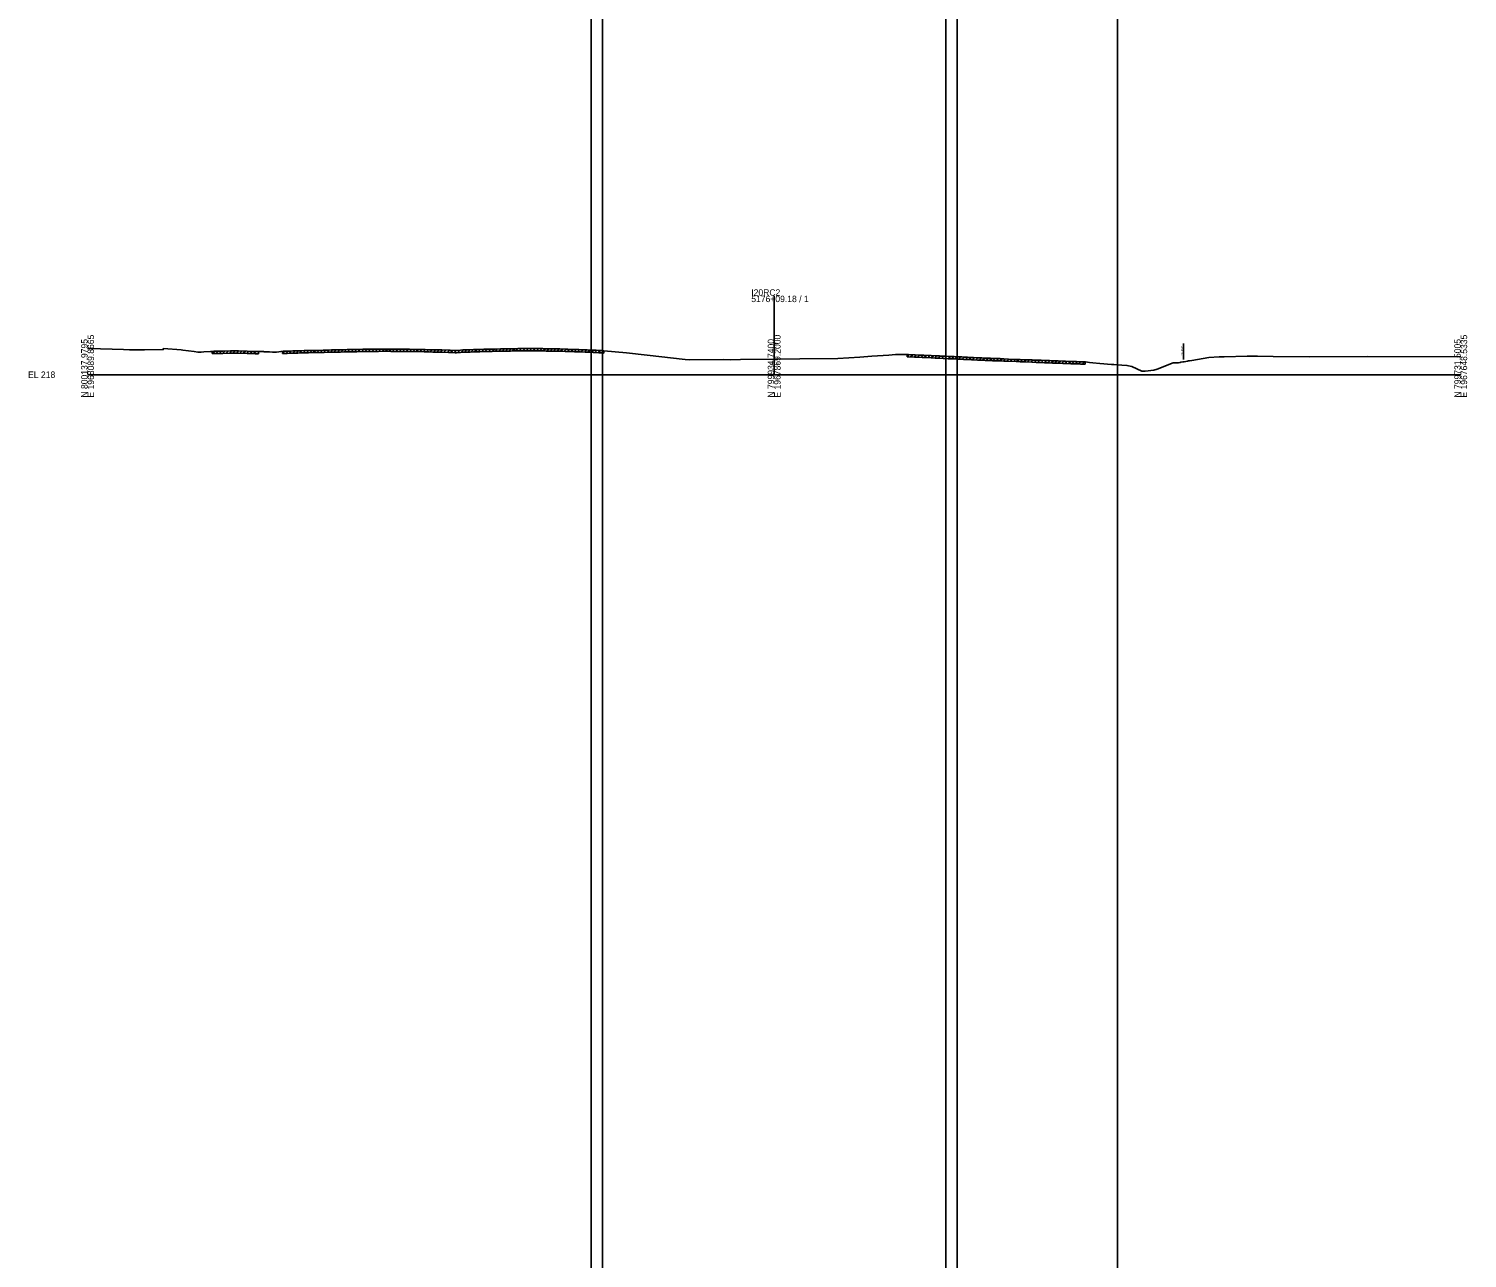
# Model space of a CAD drawing. Extents: x -119 to 6018, y -82 to 34226.
# Drawn here: x -26 to 603, y 32614 to 33151 of the extents above; entities that cross this region are included whole.
import ezdxf

# ---------------------------------------------------------------- set-up
doc = ezdxf.new("R2010")
doc.units = 0
for name, color, linetype in [('Default', 7, 'Continuous'), ('RD_GPK_XS_Cell', 7, 'Continuous'), ('RD_Sketch1', 7, 'Continuous'), ('RD_XS_ExGround', 7, 'Continuous'), ('RD_XS_ExPaveRet', 7, 'Continuous'), ('RD_XS_ExRW', 7, 'Continuous'), ('RD_XS_TX_Elev_EX', 7, 'Continuous'), ('RD_XS_TX_Elev_PR', 7, 'Continuous')]:
    doc.layers.add(name, color=color, linetype=linetype)

msp = doc.modelspace()

# ---------------------------------------------------------------- linework, layer by layer
at = {"layer": 'RD_GPK_XS_Cell'}
for p, q in [((300, 33000), (300, 33034.53)), ((0, 33000), (300, 33000)), ((300, 33000), (600, 33000))]:
    msp.add_line(p, q, dxfattribs=at)
at = {"layer": 'RD_Sketch1'}
for p, q in [((220, -82), (220, 34226.15)), ((225, -82), (225, 34226.15)), ((375, -82), (375, 34226.15)), ((380, -82), (380, 34226.15)), ((450, -82), (450, 34226.15))]:
    msp.add_line(p, q, dxfattribs=at)
at = {"layer": 'RD_XS_ExGround'}
msp.add_lwpolyline([(0, 33011.47), (0.68, 33011.44), (15.74, 33011.05), (18.27, 33010.9), (24.81, 33010.9), (33.08, 33011.01), (33.18, 33011.51), (40.95, 33010.82), (41.69, 33010.74), (46.51, 33010.1), (48.14, 33009.86), (48.48, 33009.83), (49.2, 33009.88), (49.63, 33009.91), (50.78, 33009.99), (53.67, 33010.19), (54.16, 33010.2), (55.13, 33010.23), (55.72, 33010.24), (59.13, 33010.33), (62.52, 33010.4), (64.05, 33010.42), (65.99, 33010.46), (69.68, 33010.31), (72.98, 33010.2), (73.35, 33010.19), (74.85, 33010.14), (76.07, 33010.09), (76.83, 33010.07), (77.22, 33010.05), (77.94, 33010.02), (79.51, 33009.96), (80.76, 33009.91), (81.49, 33009.9), (82.15, 33009.88), (82.6, 33009.92), (85.44, 33010.24), (85.87, 33010.24), (86.51, 33010.28), (87.24, 33010.33), (88.24, 33010.35), (89.7, 33010.4), (90.81, 33010.43), (91.86, 33010.46), (93.09, 33010.5), (94.69, 33010.56), (95.35, 33010.59), (95.95, 33010.61), (96.54, 33010.62), (99.6, 33010.64), (99.9, 33010.65), (102.88, 33010.73), (103.31, 33010.74), (104.98, 33010.79), (106.63, 33010.83), (108.46, 33010.87), (110.17, 33010.9), (110.5, 33010.91), (111.93, 33010.93), (113.48, 33010.97), (114.13, 33010.98), (116.87, 33011.04), (117.3, 33011.05), (117.7, 33011.06), (120.24, 33011.1), (120.78, 33011.11), (121.41, 33011.11), (123.6, 33011.14), (125.08, 33011.16), (126.2, 33011.18), (127.1, 33011.19), (128.83, 33011.22), (129.69, 33011.23), (130.52, 33011.23), (132.48, 33011.21), (133.91, 33011.19), (135.02, 33011.18), (136.28, 33011.17), (137.34, 33011.16), (138.47, 33011.14), (139.95, 33011.13), (140.37, 33011.13), (140.71, 33011.12), (143.6, 33011.08), (144.1, 33011.07), (147.14, 33010.99), (147.48, 33010.98), (149.19, 33010.94), (150.79, 33010.91), (152.66, 33010.87), (154.8, 33010.83), (157.66, 33010.71), (158.38, 33010.68), (160.56, 33010.61), (161.17, 33010.59), (162.94, 33010.73), (163.99, 33010.8), (164.77, 33010.82), (165.68, 33010.85), (167.24, 33010.92), (168.61, 33010.95), (169.43, 33010.98), (170.36, 33011.01), (171.33, 33011.04), (173.18, 33011.09), (173.92, 33011.12), (174.7, 33011.14), (176.84, 33011.2), (177.42, 33011.22), (178.06, 33011.23), (180.47, 33011.3), (181.45, 33011.32), (184.04, 33011.35), (184.84, 33011.36), (186.31, 33011.37), (187.72, 33011.38), (188.16, 33011.39), (189.83, 33011.4), (191.7, 33011.43), (195.23, 33011.45), (196.97, 33011.42), (198.48, 33011.4), (198.94, 33011.39), (200.45, 33011.36), (201.87, 33011.34), (202.78, 33011.32), (205.27, 33011.27), (206.35, 33011.25), (208.66, 33011.19), (209.89, 33011.15), (212.03, 33011.07), (212.77, 33011.04), (213.67, 33011), (214.64, 33010.97), (215.43, 33010.94), (217.46, 33010.87), (218.29, 33010.84), (220.97, 33010.74), (222.25, 33010.68), (223.43, 33010.62), (224.74, 33010.54), (225.59, 33010.48), (235.54, 33009.52), (244.53, 33008.58), (261.06, 33006.63), (263.01, 33006.43), (277.93, 33006.58), (281.1, 33006.54), (285.32, 33006.64), (300, 33006.81), (311.27, 33006.93), (327.81, 33007.02), (337.45, 33007.69), (342.63, 33008.06), (350.16, 33008.48), (352.98, 33008.79), (355.58, 33008.8), (358.11, 33008.84), (358.72, 33008.81), (361.27, 33008.71), (361.58, 33008.7), (363.34, 33008.61), (364.65, 33008.54), (364.98, 33008.52), (365.47, 33008.5), (368.66, 33008.34), (370.31, 33008.27), (372.08, 33008.18), (372.39, 33008.17), (373.86, 33008.1), (375.22, 33008.04), (376.08, 33008), (378.64, 33007.9), (379.76, 33007.85), (382.02, 33007.74), (382.69, 33007.71), (383.43, 33007.67), (384.47, 33007.62), (385.42, 33007.58), (386.24, 33007.54), (387.13, 33007.5), (388.8, 33007.42), (390.81, 33007.33), (391.52, 33007.3), (392.17, 33007.27), (393.3, 33007.22), (394.52, 33007.17), (395.06, 33007.15), (395.56, 33007.12), (396.83, 33007.08), (398.21, 33007.03), (398.6, 33007.02), (398.95, 33007), (400.36, 33006.94), (402.37, 33006.86), (405.77, 33006.71), (407.46, 33006.64), (409.28, 33006.57), (412.54, 33006.44), (412.94, 33006.42), (414.51, 33006.37), (415.93, 33006.32), (416.26, 33006.31), (416.63, 33006.3), (418.07, 33006.24), (419.36, 33006.2), (419.84, 33006.18), (420.36, 33006.16), (421.61, 33006.11), (422.79, 33006.06), (424.03, 33006.02), (426.17, 33005.94), (427.35, 33005.9), (429.65, 33005.82), (430.03, 33005.8), (430.67, 33005.78), (432.14, 33005.72), (432.99, 33005.68), (433.79, 33005.65), (435.87, 33005.57), (436.09, 33005.6), (437.76, 33005.39), (439.23, 33005.21), (442.36, 33004.83), (447.47, 33004.46), (448.44, 33004.39), (449.8, 33004.29), (454.16, 33004.07), (456.32, 33003.55), (460.65, 33001.53), (462.1, 33001.49), (465.94, 33001.91), (467.31, 33002.35), (474.4, 33005.25), (476.71, 33005.26), (477.37, 33005.37), (477.75, 33005.44), (478.51, 33005.57), (479.13, 33005.68), (480.58, 33005.93), (480.98, 33006), (481.42, 33006.08), (482.56, 33006.28), (489.95, 33007.56), (494.42, 33007.77), (496.7, 33007.87), (506.75, 33008.16), (511.14, 33008.14), (518.02, 33007.98), (533.9, 33007.78), (559.34, 33007.9), (600, 33007.84)], dxfattribs=at)
at = {"layer": 'RD_XS_ExPaveRet'}
for p, q in [((94.14, 33009.54), (95.18, 33010.58)), ((95.64, 33009.6), (96.66, 33010.62)), ((97.14, 33009.62), (98.15, 33010.63)), ((98.64, 33009.64), (99.65, 33010.65)), ((100.14, 33009.66), (101.17, 33010.69)), ((101.64, 33009.7), (102.67, 33010.73)), ((103.14, 33009.74), (104.17, 33010.77)), ((104.64, 33009.78), (105.67, 33010.81)), ((106.14, 33009.82), (107.16, 33010.84)), ((107.64, 33009.85), (108.66, 33010.87)), ((109.14, 33009.88), (110.16, 33010.9)), ((110.64, 33009.91), (111.66, 33010.93)), ((112.14, 33009.94), (113.16, 33010.96)), ((113.64, 33009.97), (114.66, 33010.99)), ((115.14, 33010), (116.16, 33011.02)), ((116.64, 33010.03), (117.66, 33011.06)), ((118.14, 33010.07), (119.16, 33011.08)), ((119.64, 33010.09), (120.66, 33011.11)), ((121.14, 33010.11), (122.15, 33011.12)), ((122.64, 33010.13), (123.65, 33011.14)), ((124.14, 33010.15), (125.16, 33011.16)), ((125.64, 33010.17), (126.66, 33011.18)), ((127.14, 33010.19), (128.16, 33011.21)), ((128.64, 33010.21), (129.66, 33011.23)), ((130.14, 33010.23), (131.14, 33011.23)), ((131.64, 33010.22), (132.63, 33011.21)), ((133.14, 33010.2), (134.13, 33011.19)), ((134.64, 33010.18), (135.63, 33011.17)), ((136.14, 33010.17), (137.13, 33011.16)), ((137.64, 33010.15), (138.63, 33011.14)), ((139.14, 33010.14), (140.13, 33011.13)), ((140.64, 33010.12), (141.63, 33011.11)), ((142.14, 33010.1), (143.13, 33011.09)), ((143.64, 33010.08), (144.62, 33011.06)), ((145.14, 33010.04), (146.12, 33011.02)), ((146.64, 33010), (147.62, 33010.98)), ((148.14, 33009.97), (149.12, 33010.95)), ((149.64, 33009.94), (150.62, 33010.91)), ((151.14, 33009.9), (152.12, 33010.88)), ((152.64, 33009.87), (153.62, 33010.85)), ((154.14, 33009.84), (155.11, 33010.81)), ((155.64, 33009.79), (156.6, 33010.75)), ((157.14, 33009.73), (158.1, 33010.69)), ((158.64, 33009.67), (159.61, 33010.64)), ((160.14, 33009.62), (161.11, 33010.59)), ((161.64, 33009.62), (162.73, 33010.71)), ((163.14, 33009.74), (164.21, 33010.81)), ((164.64, 33009.82), (165.67, 33010.85)), ((166.14, 33009.87), (167.18, 33010.91)), ((167.64, 33009.93), (168.67, 33010.95)), ((169.14, 33009.97), (170.18, 33011.01)), ((170.64, 33010.02), (171.67, 33011.05)), ((172.14, 33010.06), (173.17, 33011.09)), ((173.64, 33010.11), (174.67, 33011.14)), ((175.14, 33010.15), (176.17, 33011.18)), ((176.64, 33010.19), (177.67, 33011.22)), ((178.14, 33010.24), (179.17, 33011.26)), ((179.64, 33010.28), (180.67, 33011.3)), ((181.14, 33010.31), (182.16, 33011.33)), ((182.64, 33010.33), (183.65, 33011.35)), ((184.14, 33010.35), (185.15, 33011.36)), ((185.64, 33010.37), (186.65, 33011.37)), ((187.14, 33010.38), (188.15, 33011.39)), ((188.64, 33010.39), (189.65, 33011.4)), ((190.14, 33010.41), (191.15, 33011.42)), ((191.64, 33010.43), (192.65, 33011.43)), ((193.14, 33010.44), (194.15, 33011.44)), ((194.64, 33010.45), (195.64, 33011.45)), ((196.14, 33010.44), (197.12, 33011.42)), ((197.64, 33010.41), (198.62, 33011.39)), ((199.14, 33010.38), (200.12, 33011.37)), ((200.64, 33010.36), (201.62, 33011.34)), ((202.14, 33010.33), (203.12, 33011.31)), ((203.64, 33010.3), (204.62, 33011.28)), ((205.14, 33010.27), (206.12, 33011.26)), ((206.64, 33010.24), (207.62, 33011.22)), ((208.14, 33010.2), (209.11, 33011.18)), ((209.64, 33010.16), (210.61, 33011.12)), ((211.14, 33010.1), (212.11, 33011.06)), ((212.64, 33010.04), (213.6, 33011.01)), ((214.14, 33009.99), (215.1, 33010.95)), ((215.64, 33009.93), (216.61, 33010.9)), ((217.14, 33009.88), (218.11, 33010.85)), ((218.64, 33009.83), (219.6, 33010.79)), ((220.14, 33009.77), (221.1, 33010.73)), ((221.64, 33009.71), (222.6, 33010.67)), ((223.14, 33009.64), (224.09, 33010.58)), ((54.51, 33009.21), (55.54, 33010.24)), ((54.51, 33009.21), (54.51, 33010.21)), ((54.51, 33009.21), (55.13, 33009.23)), ((55.13, 33009.23), (55.72, 33009.24)), ((55.72, 33009.24), (59.13, 33009.33)), ((56.01, 33009.25), (57.04, 33010.27)), ((57.51, 33009.29), (58.54, 33010.31)), ((59.01, 33009.32), (60.04, 33010.35)), ((59.13, 33009.33), (62.52, 33009.4)), ((60.51, 33009.36), (61.54, 33010.38)), ((62.01, 33009.39), (63.03, 33010.41)), ((62.52, 33009.4), (64.05, 33009.42)), ((63.51, 33009.41), (64.53, 33010.43)), ((64.05, 33009.42), (65.99, 33009.46)), ((65.01, 33009.44), (66.03, 33010.45)), ((65.99, 33009.46), (69.68, 33009.31)), ((66.51, 33009.44), (67.48, 33010.4)), ((68.01, 33009.38), (68.98, 33010.34)), ((69.51, 33009.32), (70.48, 33010.29)), ((69.68, 33009.31), (72.98, 33009.2)), ((71.01, 33009.27), (71.98, 33010.24)), ((72.51, 33009.22), (73.48, 33010.19)), ((72.98, 33009.2), (73.35, 33009.19)), ((73.35, 33009.19), (74.63, 33009.14)), ((74.63, 33010.14), (74.63, 33009.14)), ((85.14, 33009.21), (86.19, 33010.26)), ((85.14, 33009.21), (85.14, 33010.21)), ((85.14, 33009.21), (85.44, 33009.24)), ((85.44, 33009.24), (85.87, 33009.24)), ((85.87, 33009.24), (86.51, 33009.28)), ((86.51, 33009.28), (87.24, 33009.33)), ((86.64, 33009.29), (87.69, 33010.34)), ((87.24, 33009.33), (88.24, 33009.35)), ((88.14, 33009.35), (89.17, 33010.38)), ((88.24, 33009.35), (89.7, 33009.4)), ((89.64, 33009.39), (90.67, 33010.42)), ((89.7, 33009.4), (90.81, 33009.43)), ((90.81, 33009.43), (91.86, 33009.46)), ((91.14, 33009.44), (92.17, 33010.47)), ((91.86, 33009.46), (93.09, 33009.5)), ((92.64, 33009.48), (93.68, 33010.52)), ((93.09, 33009.5), (94.69, 33009.56)), ((94.69, 33009.56), (95.35, 33009.59)), ((95.35, 33009.59), (95.95, 33009.61)), ((95.95, 33009.61), (96.54, 33009.62)), ((96.54, 33009.62), (99.6, 33009.64)), ((99.6, 33009.64), (99.9, 33009.65)), ((99.9, 33009.65), (102.88, 33009.73)), ((102.88, 33009.73), (103.31, 33009.74)), ((103.31, 33009.74), (104.98, 33009.79)), ((104.98, 33009.79), (106.63, 33009.83)), ((106.63, 33009.83), (108.46, 33009.87)), ((108.46, 33009.87), (110.17, 33009.9)), ((110.17, 33009.9), (110.5, 33009.91)), ((110.5, 33009.91), (111.93, 33009.93)), ((111.93, 33009.93), (113.48, 33009.97)), ((113.48, 33009.97), (114.13, 33009.98)), ((114.13, 33009.98), (116.87, 33010.04)), ((116.87, 33010.04), (117.3, 33010.05)), ((117.3, 33010.05), (117.7, 33010.06)), ((117.7, 33010.06), (120.24, 33010.1)), ((120.24, 33010.1), (120.78, 33010.11)), ((120.78, 33010.11), (121.41, 33010.11)), ((121.41, 33010.11), (123.6, 33010.14)), ((123.6, 33010.14), (125.08, 33010.16)), ((125.08, 33010.16), (126.2, 33010.18)), ((126.2, 33010.18), (127.1, 33010.19)), ((127.1, 33010.19), (128.83, 33010.22)), ((128.83, 33010.22), (129.69, 33010.23)), ((129.69, 33010.23), (130.52, 33010.23)), ((130.52, 33010.23), (132.48, 33010.21)), ((132.48, 33010.21), (133.91, 33010.19)), ((133.91, 33010.19), (135.02, 33010.18)), ((135.02, 33010.18), (136.28, 33010.17)), ((136.28, 33010.17), (137.34, 33010.16)), ((137.34, 33010.16), (138.47, 33010.14)), ((138.47, 33010.14), (139.95, 33010.13)), ((139.95, 33010.13), (140.37, 33010.13)), ((140.37, 33010.13), (140.71, 33010.12)), ((140.71, 33010.12), (143.6, 33010.08)), ((143.6, 33010.08), (144.1, 33010.07)), ((144.1, 33010.07), (147.14, 33009.99)), ((147.14, 33009.99), (147.48, 33009.98)), ((147.48, 33009.98), (149.19, 33009.94)), ((149.19, 33009.94), (150.79, 33009.91)), ((150.79, 33009.91), (152.66, 33009.87)), ((152.66, 33009.87), (154.8, 33009.83)), ((154.8, 33009.83), (157.66, 33009.71)), ((157.66, 33009.71), (158.38, 33009.68)), ((158.38, 33009.68), (160.56, 33009.61)), ((160.56, 33009.61), (161.17, 33009.59)), ((161.17, 33009.59), (162.94, 33009.73)), ((162.94, 33009.73), (163.99, 33009.8)), ((163.99, 33009.8), (164.77, 33009.82)), ((164.77, 33009.82), (165.68, 33009.85)), ((165.68, 33009.85), (167.24, 33009.92)), ((167.24, 33009.92), (168.61, 33009.95)), ((168.61, 33009.95), (169.43, 33009.98)), ((169.43, 33009.98), (170.36, 33010.01)), ((170.36, 33010.01), (171.33, 33010.04)), ((171.33, 33010.04), (173.18, 33010.09)), ((173.18, 33010.09), (173.92, 33010.12)), ((173.92, 33010.12), (174.7, 33010.14)), ((174.7, 33010.14), (176.84, 33010.2)), ((176.84, 33010.2), (177.42, 33010.22)), ((177.42, 33010.22), (178.06, 33010.23)), ((178.06, 33010.23), (180.47, 33010.3)), ((180.47, 33010.3), (181.45, 33010.32)), ((181.45, 33010.32), (184.04, 33010.35)), ((184.04, 33010.35), (184.84, 33010.36)), ((184.84, 33010.36), (186.31, 33010.37)), ((186.31, 33010.37), (187.72, 33010.38)), ((187.72, 33010.38), (188.16, 33010.39)), ((188.16, 33010.39), (189.83, 33010.4)), ((189.83, 33010.4), (191.7, 33010.43)), ((191.7, 33010.43), (195.23, 33010.45)), ((195.23, 33010.45), (196.97, 33010.42)), ((196.97, 33010.42), (198.48, 33010.4)), ((198.48, 33010.4), (198.94, 33010.39)), ((198.94, 33010.39), (200.45, 33010.36)), ((200.45, 33010.36), (201.87, 33010.34)), ((201.87, 33010.34), (202.78, 33010.32)), ((202.78, 33010.32), (205.27, 33010.27)), ((205.27, 33010.27), (206.35, 33010.25)), ((206.35, 33010.25), (208.66, 33010.19)), ((208.66, 33010.19), (209.89, 33010.15)), ((209.89, 33010.15), (212.03, 33010.07)), ((212.03, 33010.07), (212.77, 33010.04)), ((212.77, 33010.04), (213.67, 33010)), ((213.67, 33010), (214.64, 33009.97)), ((214.64, 33009.97), (215.43, 33009.94)), ((215.43, 33009.94), (217.46, 33009.87)), ((217.46, 33009.87), (218.29, 33009.84)), ((218.29, 33009.84), (220.97, 33009.74)), ((220.97, 33009.74), (222.25, 33009.68)), ((222.25, 33009.68), (223.43, 33009.62)), ((223.43, 33009.62), (224.74, 33009.54)), ((224.64, 33009.55), (225.58, 33010.48)), ((224.74, 33009.54), (225.59, 33009.48)), ((225.59, 33010.48), (225.59, 33009.48)), ((358.11, 33007.84), (358.11, 33008.84)), ((358.11, 33007.84), (359.06, 33008.8)), ((358.11, 33007.84), (358.72, 33007.81)), ((358.72, 33007.81), (361.27, 33007.71)), ((359.61, 33007.77), (360.57, 33008.73)), ((361.11, 33007.71), (362.07, 33008.67)), ((361.27, 33007.71), (361.58, 33007.7)), ((361.58, 33007.7), (363.34, 33007.61)), ((362.61, 33007.65), (363.56, 33008.6)), ((363.34, 33007.61), (364.65, 33007.54)), ((364.11, 33007.57), (365.05, 33008.52)), ((364.65, 33007.54), (364.98, 33007.52)), ((364.98, 33007.52), (365.47, 33007.5)), ((365.47, 33007.5), (368.66, 33007.34)), ((365.61, 33007.49), (366.56, 33008.45)), ((367.11, 33007.42), (368.06, 33008.37)), ((368.61, 33007.34), (369.57, 33008.3)), ((368.66, 33007.34), (370.31, 33007.27)), ((370.11, 33007.27), (371.06, 33008.23)), ((370.31, 33007.27), (372.08, 33007.18)), ((371.61, 33007.21), (372.56, 33008.16)), ((372.08, 33007.18), (372.39, 33007.17)), ((372.39, 33007.17), (373.86, 33007.1)), ((373.11, 33007.14), (374.07, 33008.09)), ((373.86, 33007.1), (375.22, 33007.04)), ((374.61, 33007.07), (375.57, 33008.03)), ((375.22, 33007.04), (376.08, 33007)), ((376.08, 33007), (378.64, 33006.9)), ((376.11, 33007), (377.07, 33007.96)), ((377.61, 33006.94), (378.57, 33007.9)), ((378.64, 33006.9), (379.76, 33006.85)), ((379.11, 33006.88), (380.06, 33007.83)), ((379.76, 33006.85), (382.02, 33006.74)), ((380.61, 33006.81), (381.57, 33007.76)), ((382.02, 33006.74), (382.69, 33006.71)), ((382.11, 33006.74), (383.06, 33007.69)), ((382.69, 33006.71), (383.43, 33006.67)), ((383.43, 33006.67), (384.47, 33006.62)), ((383.61, 33006.66), (384.56, 33007.62)), ((384.47, 33006.62), (385.42, 33006.58)), ((385.11, 33006.59), (386.06, 33007.55)), ((385.42, 33006.58), (386.24, 33006.54)), ((386.24, 33006.54), (387.13, 33006.5)), ((386.61, 33006.52), (387.56, 33007.48)), ((387.13, 33006.5), (388.8, 33006.42)), ((388.11, 33006.45), (389.06, 33007.41)), ((388.8, 33006.42), (390.81, 33006.33)), ((389.61, 33006.38), (390.57, 33007.34)), ((390.81, 33006.33), (391.52, 33006.3)), ((391.11, 33006.32), (392.07, 33007.27)), ((391.52, 33006.3), (392.17, 33006.27)), ((392.17, 33006.27), (393.3, 33006.22)), ((392.61, 33006.25), (393.57, 33007.21)), ((393.3, 33006.22), (394.52, 33006.17)), ((394.11, 33006.19), (395.07, 33007.15)), ((394.52, 33006.17), (395.06, 33006.15)), ((395.06, 33006.15), (395.56, 33006.12)), ((395.56, 33006.12), (396.83, 33006.08)), ((395.61, 33006.12), (396.57, 33007.09)), ((396.83, 33006.08), (398.21, 33006.03)), ((397.11, 33006.07), (398.07, 33007.03)), ((398.21, 33006.03), (398.6, 33006.02)), ((398.6, 33006.02), (398.95, 33006)), ((398.61, 33006.02), (399.57, 33006.98)), ((398.95, 33006), (400.36, 33005.94)), ((400.11, 33005.95), (401.07, 33006.91)), ((400.36, 33005.94), (402.37, 33005.86)), ((401.61, 33005.89), (402.57, 33006.85)), ((402.37, 33005.86), (405.77, 33005.71)), ((403.11, 33005.83), (404.07, 33006.78)), ((404.61, 33005.76), (405.57, 33006.72)), ((405.77, 33005.71), (407.46, 33005.64)), ((406.11, 33005.7), (407.07, 33006.66)), ((407.46, 33005.64), (409.28, 33005.57)), ((407.61, 33005.63), (408.57, 33006.6)), ((409.11, 33005.57), (410.07, 33006.54)), ((409.28, 33005.57), (412.54, 33005.44)), ((410.61, 33005.51), (411.57, 33006.48)), ((412.11, 33005.45), (413.07, 33006.42)), ((412.54, 33005.44), (412.94, 33005.42)), ((412.94, 33005.42), (414.51, 33005.37)), ((413.61, 33005.4), (414.58, 33006.37)), ((414.51, 33005.37), (415.93, 33005.32)), ((415.11, 33005.35), (416.07, 33006.32)), ((415.93, 33005.32), (416.26, 33005.31)), ((416.26, 33005.31), (416.63, 33005.3)), ((416.61, 33005.3), (417.57, 33006.26)), ((416.63, 33005.3), (418.07, 33005.24)), ((418.07, 33005.24), (419.36, 33005.2)), ((418.11, 33005.24), (419.07, 33006.21)), ((419.36, 33005.2), (419.84, 33005.18)), ((419.61, 33005.19), (420.57, 33006.15)), ((419.84, 33005.18), (420.36, 33005.16)), ((420.36, 33005.16), (421.61, 33005.11)), ((421.11, 33005.13), (422.07, 33006.09)), ((421.61, 33005.11), (422.79, 33005.06)), ((422.61, 33005.07), (423.57, 33006.03)), ((422.79, 33005.06), (424.03, 33005.02)), ((424.03, 33005.02), (426.17, 33004.94)), ((424.11, 33005.01), (425.07, 33005.98)), ((425.61, 33004.96), (426.57, 33005.92)), ((426.17, 33004.94), (427.35, 33004.9)), ((427.11, 33004.91), (428.08, 33005.87)), ((427.35, 33004.9), (429.65, 33004.82)), ((428.61, 33004.86), (429.58, 33005.82)), ((429.65, 33004.82), (430.03, 33004.8)), ((430.03, 33004.8), (430.67, 33004.78)), ((430.11, 33004.8), (431.07, 33005.76)), ((430.67, 33004.78), (432.14, 33004.72)), ((431.61, 33004.74), (432.57, 33005.7)), ((432.14, 33004.72), (432.99, 33004.68)), ((432.99, 33004.68), (433.79, 33004.65)), ((433.11, 33004.68), (434.07, 33005.64)), ((433.79, 33004.65), (435.87, 33004.57)), ((434.61, 33004.62), (435.57, 33005.58)), ((435.87, 33005.57), (435.87, 33004.57))]:
    msp.add_line(p, q, dxfattribs=at)
at = {"layer": 'RD_XS_ExRW'}
msp.add_line((478.91, 33006.64), (478.91, 33013.64), dxfattribs=at)

# ---------------------------------------------------------------- texts
at = {"layer": 'Default'}
msp.add_text('-', height=0.0001, dxfattribs=at).set_placement((0, 33000))
at = {"layer": 'RD_GPK_XS_Cell'}
for s, p in [('I20RC2', (290, 33034.53)), ('5176+09.18 / 1', (290, 33031.73)), ('EL 218', (-26, 32998.6))]:
    msp.add_text(s, height=2.8, dxfattribs=at).set_placement(p)
for s, p in [('E 1968089.8665', (2.8, 32990)), ('E 1967869.2000', (302.8, 32990)), ('E 1967648.5335', (602.8, 32990)), ('N 800137.9795', (0, 32990)), ('N 799934.7400', (300, 32990)), ('N 799731.5005', (600, 32990))]:
    msp.add_text(s, height=2.8, rotation=90, dxfattribs=at).set_placement(p)
at = {"layer": 'RD_XS_ExRW'}
msp.add_text('EX. R/W ', height=0.75, rotation=90, dxfattribs=at).set_placement((478.59, 33008.31))
at = {"layer": 'RD_XS_TX_Elev_EX'}
msp.add_text('224.81', height=1, dxfattribs=at).set_placement((298.05, 33004.31))
at = {"layer": 'RD_XS_TX_Elev_PR'}
msp.add_text(' 225.50', height=1, rotation=90, dxfattribs=at).set_placement((301, 33009.5))

doc.saveas('drawing.dxf')
